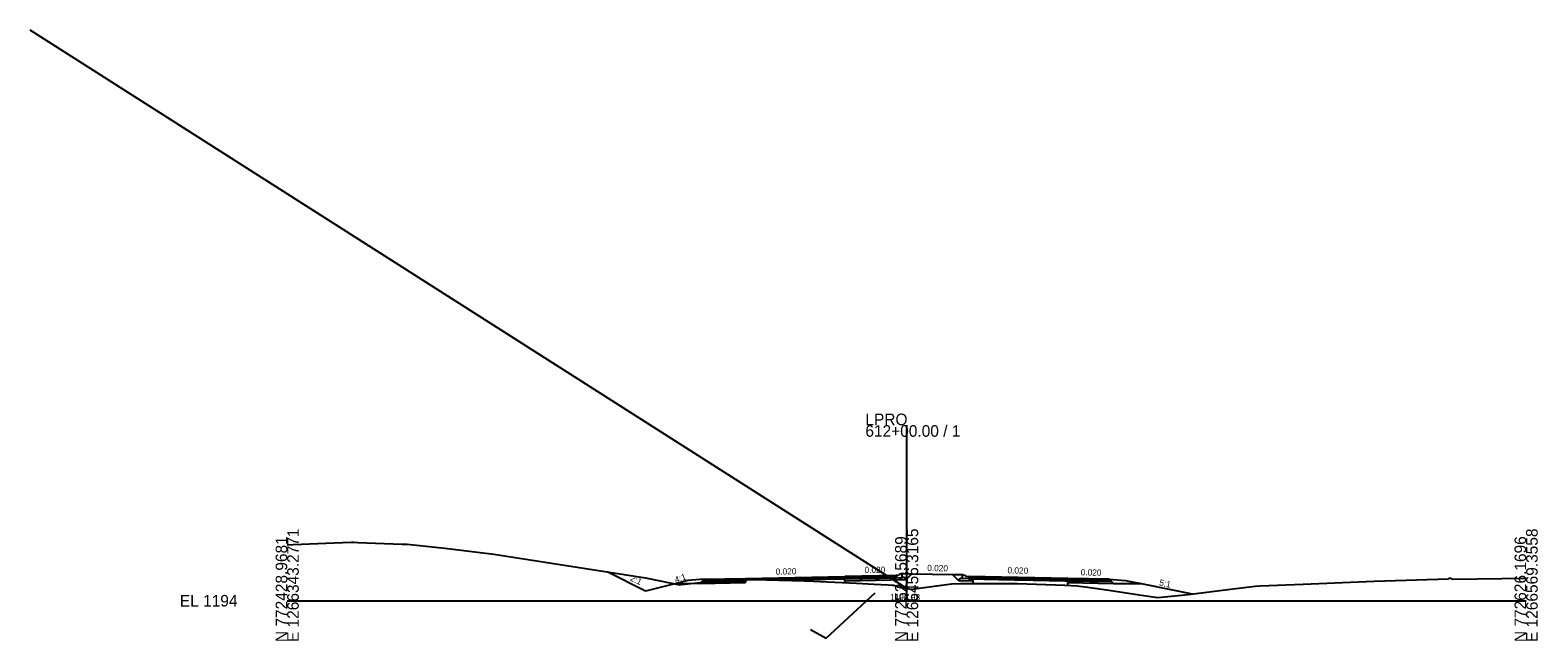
# Model space of a CAD drawing. Extents: x -3833 to 1267678, y -522 to 773248.
# Drawn here: x 1937.8 to 2302.8, y 2990.3 to 3138 of the extents above; entities that cross this region are included whole.
import ezdxf

# ---------------------------------------------------------------- set-up
doc = ezdxf.new("R2010")
doc.units = 0
for name, color, linetype in [('Exist Cross Section Cell', 7, 'Continuous'), ('Exist XS Center Line Elevation Label', 7, 'Continuous'), ('Exist XS Ground Line', 7, 'Continuous'), ('Prop CMT DNC', 7, 'Continuous'), ('Prop CMT Pvmt Course 1', 7, 'Continuous'), ('Prop CMT Pvmt Course 2', 7, 'Continuous'), ('Prop CMT Pvmt Course 3', 7, 'Continuous'), ('Prop CMT Pvmt Course 4', 7, 'Continuous'), ('Prop CMT Shld Paved Course 1', 7, 'Continuous'), ('Prop CMT Shld Paved Course 2', 7, 'Continuous'), ('Prop CMT Shld Paved Course 4', 7, 'Continuous'), ('Prop CMT Slope Grass', 7, 'Continuous'), ('Prop CMT Subgrade Earthwork', 7, 'Continuous'), ('Prop Conc Curb and Gutter', 7, 'Continuous'), ('Prop Conc Island Cover', 7, 'Continuous'), ('Prop Corridor Mesh Bottom', 7, 'Continuous'), ('Prop XS Ditch Slope Text', 7, 'Continuous'), ('Prop XS Finish Grade', 7, 'Continuous'), ('Prop XS SE Text', 7, 'Continuous'), ('Scratch_Level_1', 7, 'Continuous'), ('Scratch_Level_5', 7, 'Continuous')]:
    doc.layers.add(name, color=color, linetype=linetype)

msp = doc.modelspace()

# ---------------------------------------------------------------- linework, layer by layer
at = {"layer": 'Exist Cross Section Cell'}
for p, q in [((2150, 3000), (2150, 3042.48)), ((2000, 3000), (2150, 3000)), ((2150, 3000), (2300, 3000))]:
    msp.add_line(p, q, dxfattribs=at)
at = {"layer": 'Exist XS Ground Line'}
for p, q in [((2000, 3013.56), (2001.47, 3013.61)), ((2001.47, 3013.61), (2011.4, 3013.99)), ((2011.4, 3013.99), (2015.59, 3014.14)), ((2015.59, 3014.14), (2016.08, 3014.16)), ((2016.08, 3014.16), (2017.09, 3014.12)), ((2017.09, 3014.12), (2027.82, 3013.73)), ((2027.82, 3013.73), (2028.52, 3013.72)), ((2028.52, 3013.72), (2029.08, 3013.71)), ((2029.08, 3013.71), (2038.17, 3012.72)), ((2038.17, 3012.72), (2050.02, 3011.26)), ((2050.02, 3011.26), (2086.74, 3005.56)), ((2086.74, 3005.56), (2087.17, 3005.49)), ((2087.17, 3005.49), (2095.03, 3003.87)), ((2095.43, 3003.91), (2103.98, 3004.78)), ((2103.98, 3004.78), (2106.13, 3005)), ((2106.13, 3005), (2107.64, 3005.16)), ((2107.64, 3005.16), (2113.07, 3005.15)), ((2113.07, 3005.15), (2125.28, 3004.83)), ((2125.28, 3004.83), (2125.65, 3004.81)), ((2125.65, 3004.81), (2137.82, 3004.24)), ((2246.05, 3004), (2263.18, 3004.75)), ((2263.18, 3004.75), (2281.18, 3005.32)), ((2281.18, 3005.32), (2281.56, 3005.55)), ((2281.56, 3005.55), (2282.26, 3005.26)), ((2282.26, 3005.26), (2300, 3005.49)), ((2095.03, 3003.87), (2095.43, 3003.91)), ((2137.82, 3004.24), (2142.09, 3004.04)), ((2142.09, 3004.04), (2145.48, 3003.85)), ((2145.48, 3003.85), (2146.55, 3003.78)), ((2146.55, 3003.78), (2146.91, 3003.74)), ((2146.91, 3003.74), (2147.86, 3003.39)), ((2147.86, 3003.39), (2148.51, 3003.19)), ((2148.51, 3003.19), (2150.07, 3002.97)), ((2150.07, 3002.97), (2151.15, 3002.81)), ((2151.15, 3002.81), (2156.08, 3003.47)), ((2156.08, 3003.47), (2159.61, 3003.96)), ((2159.61, 3003.96), (2160.89, 3004.12)), ((2160.89, 3004.12), (2163.04, 3004.17)), ((2163.04, 3004.17), (2164.05, 3004.2)), ((2164.05, 3004.2), (2176.01, 3004.21)), ((2176.01, 3004.21), (2176.87, 3004.18)), ((2176.87, 3004.18), (2188.3, 3003.79)), ((2188.3, 3003.79), (2191.31, 3003.58)), ((2191.31, 3003.58), (2191.85, 3003.55)), ((2191.85, 3003.55), (2193.32, 3003.34)), ((2193.32, 3003.34), (2199.55, 3002.46)), ((2199.55, 3002.46), (2206.28, 3001.47)), ((2206.28, 3001.47), (2210.81, 3000.77)), ((2210.81, 3000.77), (2218.2, 3001.55)), ((2218.2, 3001.55), (2228.45, 3002.78)), ((2228.45, 3002.78), (2234.38, 3003.49)), ((2234.38, 3003.49), (2235.58, 3003.6)), ((2235.58, 3003.6), (2246.05, 3004))]:
    msp.add_line(p, q, dxfattribs=at)
at = {"layer": 'Prop CMT Pvmt Course 1'}
for p, q in [((2111, 3005.42), (2135, 3005.9)), ((2135, 3005.65), (2111, 3005.17)), ((2111, 3005.17), (2111, 3005.42)), ((2111, 3005.42), (2111, 3005.42)), ((2135, 3005.9), (2135, 3005.9)), ((2135, 3005.9), (2135, 3005.9)), ((2135, 3005.9), (2135, 3005.65)), ((2135, 3005.65), (2135, 3005.65)), ((2189, 3005.42), (2165, 3005.9)), ((2165, 3005.9), (2165, 3005.9)), ((2165, 3005.9), (2165, 3005.9)), ((2165, 3005.9), (2165, 3005.65)), ((2165, 3005.65), (2189, 3005.17)), ((2165, 3005.65), (2165, 3005.65)), ((2189, 3005.17), (2189, 3005.42)), ((2189, 3005.42), (2189, 3005.42))]:
    msp.add_line(p, q, dxfattribs=at)
at = {"layer": 'Prop CMT Pvmt Course 2'}
for p, q in [((2147.44, 3005.9), (2135, 3005.65)), ((2135, 3005.65), (2135, 3005.65)), ((2135, 3005.65), (2135, 3005.32)), ((2135, 3005.32), (2147.44, 3005.57)), ((2135, 3005.32), (2135, 3005.32)), ((2150, 3005.62), (2150, 3005.62)), ((2150, 3005.62), (2150, 3005.62)), ((2165, 3005.32), (2165, 3005.65)), ((2165, 3005.65), (2165, 3005.65)), ((2165, 3005.32), (2165, 3005.32))]:
    msp.add_line(p, q, dxfattribs=at)
at = {"layer": 'Prop CMT Pvmt Course 3'}
for p, q in [((2147.49, 3005.57), (2147.44, 3005.57)), ((2149.74, 3005.32), (2149.45, 3005.61)), ((2162.7, 3005.07), (2162.99, 3005.36)), ((2166, 3005.88), (2166, 3004.84))]:
    msp.add_line(p, q, dxfattribs=at)
at = {"layer": 'Prop CMT Pvmt Course 4'}
for p, q in [((2135, 3004.38), (2135, 3005.32)), ((2135, 3005.32), (2135, 3005.32)), ((2135, 3005.32), (2135, 3005.32)), ((2149.45, 3005.61), (2148.95, 3005.6)), ((2149.45, 3005.61), (2149.9, 3005.16)), ((2150, 3005.62), (2150, 3005.62)), ((2150, 3005.62), (2150, 3005.62)), ((2162.99, 3005.36), (2162.54, 3004.91)), ((2163.49, 3005.35), (2162.99, 3005.36)), ((2165, 3005.32), (2165, 3005.32)), ((2165, 3005.32), (2165, 3005.32))]:
    msp.add_line(p, q, dxfattribs=at)
at = {"layer": 'Prop CMT Shld Paved Course 1'}
for p, q in [((2100.74, 3004.97), (2101, 3005.22)), ((2111, 3005.17), (2100.74, 3004.97)), ((2101, 3005.22), (2111, 3005.42)), ((2111, 3005.42), (2111, 3005.17)), ((2147.44, 3006.15), (2135, 3005.9)), ((2135, 3005.9), (2135, 3005.9)), ((2135, 3005.9), (2135, 3005.65)), ((2150, 3005.95), (2150, 3005.95)), ((2165, 3005.65), (2165, 3005.9)), ((2165, 3005.9), (2165, 3005.9)), ((2189, 3005.42), (2189, 3005.17)), ((2199, 3005.22), (2189, 3005.42)), ((2189, 3005.17), (2199.26, 3004.97)), ((2199.26, 3004.97), (2199, 3005.22))]:
    msp.add_line(p, q, dxfattribs=at)
at = {"layer": 'Prop CMT Shld Paved Course 2'}
for p, q in [((2100.41, 3004.63), (2100.74, 3004.97)), ((2111, 3004.84), (2100.41, 3004.63)), ((2100.74, 3004.97), (2111, 3005.17)), ((2113.07, 3005.21), (2111, 3005.17)), ((2111, 3005.17), (2111, 3005.17)), ((2111, 3005.17), (2111, 3005.17)), ((2111, 3005.17), (2111, 3005.15)), ((2111, 3005.17), (2111, 3004.84)), ((2111, 3005.15), (2111, 3005.15)), ((2111, 3005.15), (2113.07, 3005.15)), ((2125.07, 3005.45), (2113.07, 3005.21)), ((2113.07, 3005.21), (2113.07, 3005.21)), ((2113.07, 3005.21), (2113.07, 3005.21)), ((2113.07, 3005.15), (2113.07, 3005.15)), ((2113.07, 3005.15), (2113.07, 3005.15)), ((2113.07, 3005.15), (2118.94, 3005)), ((2118.94, 3005), (2125.07, 3005.12)), ((2118.94, 3005), (2118.94, 3005)), ((2125.28, 3005.46), (2125.07, 3005.45)), ((2125.07, 3005.45), (2125.07, 3005.45)), ((2125.07, 3005.12), (2125.07, 3005.12)), ((2125.07, 3005.12), (2125.28, 3005.12)), ((2125.65, 3005.46), (2125.28, 3005.46)), ((2125.28, 3005.12), (2125.65, 3005.13)), ((2135, 3005.65), (2125.65, 3005.46)), ((2125.65, 3005.46), (2125.65, 3005.46)), ((2125.65, 3005.13), (2135, 3005.32)), ((2125.65, 3005.13), (2125.65, 3005.13)), ((2135, 3005.32), (2135, 3005.65)), ((2135, 3005.65), (2135, 3005.65)), ((2135, 3005.65), (2135, 3005.65)), ((2135, 3005.32), (2135, 3005.32)), ((2165, 3005.65), (2165, 3005.65)), ((2165, 3005.65), (2165, 3005.65)), ((2165, 3005.65), (2165, 3005.32)), ((2165, 3005.32), (2165, 3005.32)), ((2165, 3005.32), (2176.01, 3005.1)), ((2176.87, 3005.41), (2176.01, 3005.43)), ((2176.01, 3005.43), (2176.01, 3005.43)), ((2176.01, 3005.1), (2176.01, 3005.1)), ((2176.01, 3005.1), (2176.87, 3005.08)), ((2188.3, 3005.19), (2176.87, 3005.41)), ((2176.87, 3005.41), (2176.87, 3005.41)), ((2176.87, 3005.08), (2176.87, 3005.08)), ((2176.87, 3005.08), (2188.3, 3004.85)), ((2189, 3005.17), (2188.3, 3005.19)), ((2188.3, 3005.19), (2188.3, 3005.19)), ((2188.3, 3004.85), (2188.3, 3004.85)), ((2188.3, 3004.85), (2189, 3004.84)), ((2189, 3004.84), (2189, 3005.17)), ((2189, 3005.17), (2189, 3005.17)), ((2189, 3005.17), (2189, 3005.17)), ((2189, 3005.17), (2189, 3004.84)), ((2199.26, 3004.97), (2189, 3005.17)), ((2189, 3004.84), (2189, 3004.84)), ((2189, 3004.84), (2199.59, 3004.63)), ((2199.59, 3004.63), (2199.26, 3004.97))]:
    msp.add_line(p, q, dxfattribs=at)
at = {"layer": 'Prop CMT Shld Paved Course 4'}
for p, q in [((2100.91, 3004.64), (2111, 3004.84)), ((2111, 3004.84), (2111, 3004.38)), ((2189, 3004.84), (2189, 3004.38)), ((2199.09, 3004.64), (2189, 3004.84)), ((2099.94, 3004.16), (2100.41, 3004.63)), ((2111, 3004.38), (2099.94, 3004.16)), ((2100.41, 3004.63), (2100.91, 3004.64)), ((2189, 3004.38), (2200.06, 3004.16)), ((2199.59, 3004.63), (2199.09, 3004.64)), ((2200.06, 3004.16), (2199.59, 3004.63))]:
    msp.add_line(p, q, dxfattribs=at)
at = {"layer": 'Prop CMT Slope Grass'}
for p, q in [((2101, 3005.22), (2097, 3004.9)), ((2148.95, 3006.58), (2149.33, 3006.58)), ((2149.33, 3006.58), (2151.28, 3006.54)), ((2161.08, 3006.37), (2163.49, 3006.33)), ((2199, 3005.22), (2203, 3004.9)), ((2203, 3004.9), (2206.82, 3004.14))]:
    msp.add_line(p, q, dxfattribs=at)
at = {"layer": 'Prop CMT Subgrade Earthwork'}
for p, q in [((2111, 3004.38), (2111, 3005.15)), ((2135, 3004.86), (2149.9, 3005.16)), ((2135, 3004.86), (2135, 3004.38)), ((2149.9, 3005.16), (2151.28, 3006.54)), ((2162.54, 3004.91), (2161.08, 3006.37)), ((2162.54, 3004.91), (2166, 3004.84)), ((2166, 3004.84), (2166, 3004.2)), ((2189, 3003.74), (2189, 3004.38)), ((2189, 3004.38), (2200.06, 3004.16)), ((2200.06, 3004.16), (2206.82, 3004.14))]:
    msp.add_line(p, q, dxfattribs=at)
msp.add_lwpolyline([(2094.48, 3004.27), (2099.94, 3004.16), (2111, 3004.38)], dxfattribs=at)
at = {"layer": 'Prop Conc Curb and Gutter'}
for p, q in [((2147.44, 3006.15), (2147.44, 3006.15)), ((2147.44, 3006.15), (2147.44, 3005.57)), ((2147.49, 3006.15), (2147.44, 3006.15)), ((2147.44, 3005.57), (2147.49, 3005.57)), ((2148.19, 3006.17), (2147.49, 3006.15)), ((2147.49, 3005.57), (2148.95, 3005.6)), ((2148.95, 3006.58), (2148.19, 3006.33)), ((2148.19, 3006.33), (2148.19, 3006.33)), ((2148.19, 3006.33), (2148.19, 3006.17)), ((2148.19, 3006.17), (2148.19, 3006.17)), ((2148.95, 3005.6), (2148.95, 3006.58)), ((2148.95, 3005.6), (2148.95, 3005.6)), ((2163.49, 3005.35), (2163.49, 3006.33)), ((2163.49, 3006.33), (2163.49, 3006.33)), ((2163.49, 3006.33), (2163.49, 3006.33)), ((2163.49, 3006.33), (2164.25, 3006.08)), ((2165, 3005.32), (2163.49, 3005.35)), ((2163.49, 3005.35), (2163.49, 3005.35)), ((2164.25, 3006.08), (2164.25, 3006.08)), ((2164.25, 3006.08), (2164.25, 3005.92)), ((2164.25, 3005.92), (2165, 3005.9)), ((2164.25, 3005.92), (2164.25, 3005.92)), ((2165, 3005.9), (2165, 3005.9)), ((2165, 3005.9), (2165, 3005.32))]:
    msp.add_line(p, q, dxfattribs=at)
at = {"layer": 'Prop Conc Island Cover'}
for p, q in [((2163.49, 3006.33), (2163.49, 3006.33)), ((2163.49, 3006.08), (2163.49, 3006.08))]:
    msp.add_line(p, q, dxfattribs=at)
at = {"layer": 'Prop Corridor Mesh Bottom'}
for p, q in [((2111, 3005.42), (2111, 3005.17)), ((2135, 3005.9), (2135, 3005.65)), ((2165, 3005.9), (2165, 3005.65)), ((2189, 3005.42), (2189, 3005.17))]:
    msp.add_line(p, q, dxfattribs=at)
at = {"layer": 'Prop XS Finish Grade'}
for p, q in [((2086.79, 3002.35), (2077.49, 3007)), ((2097, 3004.9), (2093.85, 3004.11)), ((2151.28, 3006.54), (2161.08, 3006.37)), ((2163.49, 3006.33), (2163.49, 3006.33)), ((2093.85, 3004.11), (2086.79, 3002.35))]:
    msp.add_line(p, q, dxfattribs=at)
msp.add_lwpolyline([(2203, 3004.9), (2208, 3003.9), (2219.16, 3001.67)], dxfattribs=at)
at = {"layer": 'Scratch_Level_1'}
msp.add_line((2150, 3002.98), (1937.75, 3138.04), dxfattribs=at)
at = {"layer": 'Scratch_Level_5'}
for p, q in [((2130.5, 2990.93), (2142.36, 3001.95)), ((2126.72, 2993.03), (2130.5, 2990.93))]:
    msp.add_line(p, q, dxfattribs=at)

# ---------------------------------------------------------------- texts
at = {"layer": 'Exist Cross Section Cell'}
for s, p in [('LPRO', (2140, 3042.48)), ('612+00.00 / 1', (2140, 3039.68)), ('EL 1194', (1974, 2998.6))]:
    msp.add_text(s, height=2.8, dxfattribs=at).set_placement(p)
for s, p in [('E 1266343.2771', (2002.8, 2990)), ('E 1266456.3165', (2152.8, 2990)), ('E 1266569.3558', (2302.8, 2990)), ('N 772428.9681', (2000, 2990)), ('N 772527.5689', (2150, 2990)), ('N 772626.1696', (2300, 2990))]:
    msp.add_text(s, height=2.8, rotation=90, dxfattribs=at).set_placement(p)
at = {"layer": 'Exist XS Center Line Elevation Label'}
msp.add_text('1196.98', height=1.5, dxfattribs=at).set_placement((2145.99, 3000.11))
at = {"layer": 'Prop CMT DNC'}
for p in [(2111, 3005.42), (2111, 3005.42), (2135, 3005.9), (2135, 3005.9), (2148.19, 3006.17), (2164.25, 3005.92), (2165, 3005.9), (2165, 3005.9), (2189, 3005.42), (2189, 3005.42), (2199, 3005.22)]:
    msp.add_text('X', height=0.00025, dxfattribs=at).set_placement(p)
at = {"layer": 'Prop XS Ditch Slope Text'}
for s, rotation, p in [('2:1', 335.1076, (2082.9, 3004.95)), ('4:1', 19.4296, (2094.12, 3004.29)), ('5:1', 347.5411, (2211.06, 3003.74))]:
    msp.add_text(s, height=1.5, rotation=rotation, dxfattribs=at).set_placement(p)
at = {"layer": 'Prop XS SE Text'}
for rotation, p in [(358.8542, (2154.97, 3007.21)), (1.397, (2118.3, 3006.29)), (0.2693, (2139.8, 3006.72)), (358.8542, (2174.4, 3006.62)), (358.8542, (2192.14, 3006.15))]:
    msp.add_text('0.020', height=1.5, rotation=rotation, dxfattribs=at).set_placement(p)

doc.saveas('drawing.dxf')
